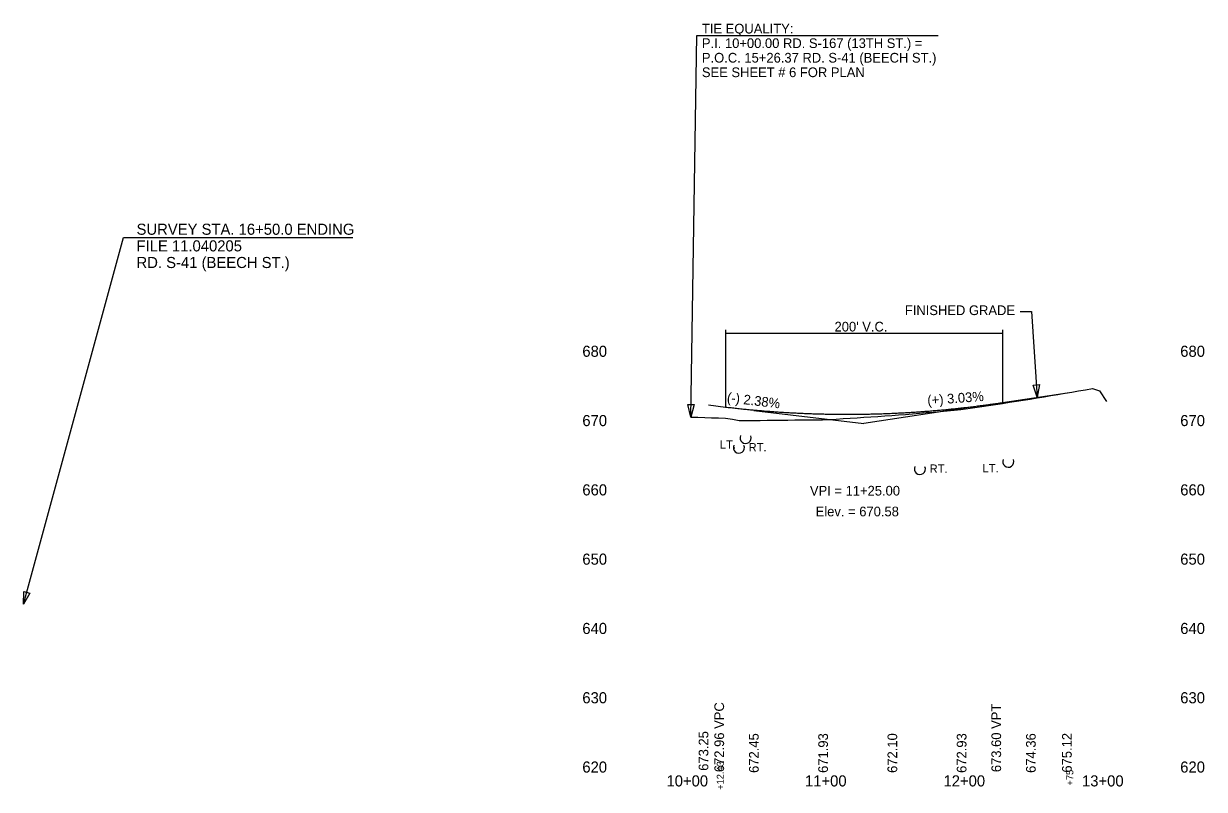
# Model space of a CAD drawing. Extents: x 16383870 to 16385930, y 46196762 to 46198956.
# Drawn here: x 16383870 to 16384722, y 46197910 to 46198462 of the extents above; entities that cross this region are included whole.
import ezdxf

# ---------------------------------------------------------------- set-up
doc = ezdxf.new("R2010")
doc.units = 0
for name, color, linetype in [('Default', 7, 'Continuous'), ('RD_DDB_ElevTX', 7, 'Continuous'), ('RD_DDB_GradeTX', 7, 'Continuous'), ('RD_DDB_Profile_EX', 7, 'Continuous'), ('RD_DDB_Profile_Lbl', 7, 'Continuous'), ('RD_DDB_Profile_PR', 7, 'Continuous'), ('RD_DDB_StaTX', 7, 'Continuous'), ('RD_DDB_StripGrade', 7, 'Continuous'), ('RD_DDB_VCLbl', 7, 'Continuous'), ('RD_PD_Final_TX', 7, 'Continuous'), ('RD_SHT_MjGrid', 7, 'Continuous'), ('RD_SHT_MnGrid', 7, 'Continuous'), ('RD_TX_Misc1', 7, 'Continuous')]:
    doc.layers.add(name, color=color, linetype=linetype)

msp = doc.modelspace()

# ---------------------------------------------------------------- linework, layer by layer
at = {"layer": 'Default'}
for centre in [(16384390.89, 46198163.18), (16384386.01, 46198156.31), (16384580.53, 46198146.07), (16384516.69, 46198140.88)]:
    msp.add_arc(centre, 3.98, 153.82804, 22.53319, dxfattribs=at)
at = {"layer": 'RD_DDB_GradeTX'}
for p in [(16384396.91, 46198183.14), (16384555.45, 46198185.66)]:
    msp.add_line(p, (16384476.35, 46198173.69), dxfattribs=at)
at = {"layer": 'RD_DDB_Profile_EX'}
msp.add_lwpolyline([(16384351.35, 46198178.32), (16384356.35, 46198178.15), (16384361.35, 46198178.08), (16384366.35, 46198177.87), (16384371.35, 46198177.66), (16384376.35, 46198177.45), (16384381.35, 46198176.92), (16384386.35, 46198175.91), (16384391.35, 46198175.81), (16384396.35, 46198175.78), (16384401.35, 46198175.94), (16384406.35, 46198176.04), (16384411.35, 46198176.09), (16384416.35, 46198176.15), (16384421.35, 46198176.21), (16384426.35, 46198176.28), (16384431.35, 46198176.33), (16384436.35, 46198176.39), (16384441.35, 46198176.45), (16384446.35, 46198176.39), (16384451.35, 46198176.59), (16384456.35, 46198176.91), (16384461.35, 46198177.22), (16384466.35, 46198177.54), (16384471.35, 46198177.86), (16384476.35, 46198178.18), (16384481.35, 46198178.5), (16384486.35, 46198178.82), (16384491.35, 46198179.13), (16384496.35, 46198179.46), (16384501.35, 46198179.85), (16384506.35, 46198180.28), (16384511.35, 46198180.7), (16384516.35, 46198181.13), (16384521.35, 46198181.55), (16384526.35, 46198181.95), (16384531.35, 46198182.38), (16384536.35, 46198182.8), (16384541.35, 46198183.22), (16384546.35, 46198183.7), (16384551.35, 46198184.44), (16384556.35, 46198185.2), (16384561.35, 46198185.97), (16384566.35, 46198186.73), (16384571.35, 46198187.48), (16384576.35, 46198188.23), (16384581.35, 46198188.99), (16384586.35, 46198189.76), (16384591.35, 46198190.52), (16384596.35, 46198191.3), (16384601.35, 46198192.15), (16384606.35, 46198193), (16384611.35, 46198193.84), (16384616.35, 46198194.69), (16384621.35, 46198195.54), (16384626.35, 46198196.39), (16384631.35, 46198197.24), (16384636.35, 46198198.09), (16384641.35, 46198198.94), (16384646.35, 46198197.31), (16384651.35, 46198189.66)], dxfattribs=at)
at = {"layer": 'RD_DDB_Profile_PR'}
for p, q in [((16384576.35, 46198188.82), (16384626.35, 46198196.39)), ((16384364.01, 46198187.05), (16384376.35, 46198185.58))]:
    msp.add_line(p, q, dxfattribs=at)
msp.add_spline([(16384376.35, 46198185.58), (16384380.35, 46198185.12), (16384384.35, 46198184.68), (16384388.35, 46198184.25), (16384392.35, 46198183.85), (16384396.35, 46198183.48), (16384400.35, 46198183.12), (16384404.35, 46198182.78), (16384408.35, 46198182.47), (16384412.35, 46198182.18), (16384416.35, 46198181.91), (16384420.35, 46198181.66), (16384424.35, 46198181.43), (16384428.35, 46198181.23), (16384432.35, 46198181.04), (16384436.35, 46198180.88), (16384440.35, 46198180.74), (16384444.35, 46198180.62), (16384448.35, 46198180.52), (16384452.35, 46198180.45), (16384456.35, 46198180.4), (16384460.35, 46198180.36), (16384464.35, 46198180.35), (16384468.35, 46198180.36), (16384472.35, 46198180.4), (16384476.35, 46198180.45), (16384480.35, 46198180.52), (16384484.35, 46198180.62), (16384488.35, 46198180.74), (16384492.35, 46198180.88), (16384496.35, 46198181.04), (16384500.35, 46198181.23), (16384504.35, 46198181.43), (16384508.35, 46198181.66), (16384512.35, 46198181.91), (16384516.35, 46198182.18), (16384520.35, 46198182.47), (16384524.35, 46198182.78), (16384528.35, 46198183.12), (16384532.35, 46198183.48), (16384536.35, 46198183.85), (16384540.35, 46198184.25), (16384544.35, 46198184.67), (16384548.35, 46198185.12), (16384552.35, 46198185.58), (16384556.35, 46198186.07), (16384560.35, 46198186.58), (16384564.35, 46198187.11), (16384568.35, 46198187.66), (16384572.35, 46198188.23), (16384576.35, 46198188.82)], degree=3, dxfattribs=at)
at = {"layer": 'RD_DDB_VCLbl'}
for p, q in [((16384376.35, 46198241.32), (16384376.35, 46198185.58)), ((16384376.35, 46198238.82), (16384576.35, 46198238.82)), ((16384576.35, 46198241.32), (16384576.35, 46198188.82))]:
    msp.add_line(p, q, dxfattribs=at)
at = {"layer": 'RD_PD_Final_TX'}
for p, q in [((16383869.63, 46198043.23), (16383941.63, 46198307.85)), ((16383941.63, 46198307.85), (16384107.22, 46198307.85))]:
    msp.add_line(p, q, dxfattribs=at)
at = {"layer": 'RD_SHT_MjGrid'}
for p, q in [((16384351.35, 46198178.32), (16384355.78, 46198453.7)), ((16384355.78, 46198453.7), (16384529.93, 46198453.7)), ((16384589.13, 46198254.58), (16384597.26, 46198254.58)), ((16384597.26, 46198254.58), (16384601.35, 46198192.61))]:
    msp.add_line(p, q, dxfattribs=at)
at = {"layer": 'RD_SHT_MnGrid'}
for points in [[(16384603, 46198201.74), (16384601.35, 46198192.61), (16384598.51, 46198201.44)], [(16384353.74, 46198187.28), (16384351.35, 46198178.32), (16384349.25, 46198187.35)], [(16383874.17, 46198051.33), (16383869.63, 46198043.23), (16383869.82, 46198052.51)]]:
    msp.add_lwpolyline(points, close=True, dxfattribs=at)

# ---------------------------------------------------------------- texts
at = {"layer": 'Default'}
for s, p in [('LT.', (16384372.3, 46198155.56)), ('RT.', (16384393.09, 46198153.53)), ('RT.', (16384523.77, 46198138.1)), ('LT.', (16384561.94, 46198138.45))]:
    msp.add_text(s, height=6, dxfattribs=at).set_placement(p)
at = {"layer": 'RD_DDB_ElevTX'}
for s, p in [('680', (16384273.02, 46198221.8)), ('680', (16384704.69, 46198221.8)), ('670', (16384273.02, 46198171.8)), ('670', (16384704.69, 46198171.8)), ('660', (16384273.02, 46198121.8)), ('660', (16384704.69, 46198121.8)), ('650', (16384273.02, 46198071.8)), ('650', (16384704.69, 46198071.8)), ('640', (16384273.02, 46198021.8)), ('640', (16384704.69, 46198021.8)), ('630', (16384273.02, 46197971.8)), ('630', (16384704.69, 46197971.8)), ('620', (16384273.02, 46197921.8)), ('620', (16384704.69, 46197921.8))]:
    msp.add_text(s, height=8, dxfattribs=at).set_placement(p)
at = {"layer": 'RD_DDB_GradeTX'}
for s, rotation, p in [('(-) 2.38%', 353.2202, (16384377.14, 46198189.1)), ('(+) 3.03%', 4.29824, (16384522.34, 46198186.91))]:
    msp.add_text(s, height=7, rotation=rotation, dxfattribs=at).set_placement(p)
at = {"layer": 'RD_DDB_Profile_Lbl'}
for s, p in [('VPI = 11+25.00', (16384437.32, 46198121.69)), ('Elev. = 670.58', (16384441.46, 46198106.69))]:
    msp.add_text(s, height=7, dxfattribs=at).set_placement(p)
for s, p in [('673.25', (16384364.01, 46197923.07)), ('675.12', (16384626.35, 46197921.75))]:
    msp.add_text(s, height=7, rotation=90, dxfattribs=at).set_placement(p)
at = {"layer": 'RD_DDB_StaTX'}
for s, p in [('10+00', (16384333.76, 46197911.8)), ('11+00', (16384433.76, 46197911.8)), ('12+00', (16384533.76, 46197911.8)), ('13+00', (16384633.76, 46197911.8))]:
    msp.add_text(s, height=8, dxfattribs=at).set_placement(p)
at = {"layer": 'RD_DDB_StripGrade'}
for s, p in [('672.96 VPC', (16384375.35, 46197922.09)), ('673.60 VPT', (16384575.35, 46197922.09)), ('672.45', (16384400.35, 46197921.55)), ('671.93', (16384450.35, 46197921.55)), ('672.10', (16384500.35, 46197921.55)), ('672.93', (16384550.35, 46197921.55)), ('674.36', (16384600.35, 46197921.55))]:
    msp.add_text(s, height=7, rotation=90, dxfattribs=at).set_placement(p)
at = {"layer": 'RD_DDB_VCLbl'}
msp.add_text("200' V.C.", height=7, dxfattribs=at).set_placement((16384455.1, 46198240.07))
at = {"layer": 'RD_PD_Final_TX'}
for s, p in [('SURVEY STA. 16+50.0 ENDING', (16383951.15, 46198309.87)), ('FILE 11.040205', (16383951.15, 46198297.87)), ('RD. S-41 (BEECH ST.)', (16383951.15, 46198285.87))]:
    msp.add_text(s, height=8, dxfattribs=at).set_placement(p)
at = {"layer": 'RD_SHT_MjGrid'}
for s, p in [('TIE EQUALITY:', (16384359.33, 46198455.12)), ('P.I. 10+00.00 RD. S-167 (13TH ST.) =', (16384359.33, 46198444.62)), ('P.O.C. 15+26.37 RD. S-41 (BEECH ST.)', (16384359.33, 46198434.12)), ('SEE SHEET # 6 FOR PLAN', (16384359.33, 46198423.62)), ('FINISHED GRADE', (16384505.86, 46198251.91))]:
    msp.add_text(s, height=7, dxfattribs=at).set_placement(p)
at = {"layer": 'RD_TX_Misc1'}
for s, p in [('+12.43', (16384375.09, 46197909.35)), ('+75', (16384627.49, 46197912.44))]:
    msp.add_text(s, height=5, rotation=90, dxfattribs=at).set_placement(p)

doc.saveas('drawing.dxf')
